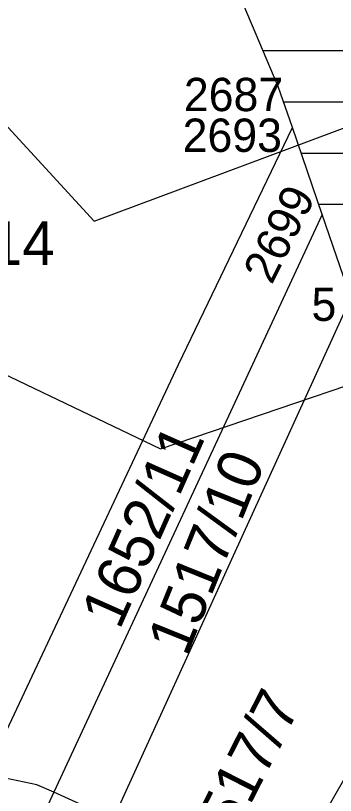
# Model space of a CAD drawing. Extents: x -553916 to -552953, y -1067469 to -1066637.
# Drawn here: x -553532.46 to -553520.01, y -1066999.11 to -1066968.69 of the extents above; entities that cross this region are included whole.
import ezdxf

# ---------------------------------------------------------------- set-up
doc = ezdxf.new("R2010")
doc.units = 0
for name, color, linetype in [('Hranice parcel', 7, 'Continuous'), ('Parcelní čísla', 7, 'Continuous'), ('Propustek', 7, 'Continuous'), ('Přejezd - štěrkové lože', 7, 'Continuous'), ('Vrstva 1', 7, 'Continuous'), ('Vrstva 60', 7, 'Continuous')]:
    doc.layers.add(name, color=color, linetype=linetype)

msp = doc.modelspace()

# ---------------------------------------------------------------- linework, layer by layer
at = {"layer": 'Hranice parcel'}
for p, q in [((-553520.52, -1066976.45), (-553530.98, -1066998.99)), ((-553519.4, -1066979.7), (-553528.66, -1067000.03)), ((-553530.98, -1066998.99), (-553538.9, -1067016.05)), ((-553528.66, -1067000.03), (-553530.98, -1066998.99))]:
    msp.add_line(p, q, dxfattribs=at)
for points in [[(-553533.63, -1066998.28), (-553526.12, -1066982.3), (-553521.68, -1066973.05)], [(-553515.43, -1066991.08), (-553526.38, -1067010.19), (-553539.65, -1067043.59), (-553548.33, -1067069.03)], [(-553530.98, -1066998.99), (-553531.64, -1066998.7), (-553533.63, -1066998.28)]]:
    msp.add_lwpolyline(points, dxfattribs=at)
at = {"layer": 'Propustek'}
msp.add_lwpolyline([(-553576.56, -1066984.514), (-553536.119, -1066969.402), (-553529.408, -1066976.709), (-553517.537, -1066972.276)], dxfattribs=at)
at = {"layer": 'Přejezd - štěrkové lože'}
msp.add_lwpolyline([(-553573.367, -1066993.961), (-553535.151, -1066981.6), (-553526.82, -1066985.587), (-553514.291, -1066981.32)], dxfattribs=at)
at = {"layer": 'Vrstva 1'}
for p, q in [((-553522.825, -1066970.052), (-553518.361, -1066970.052)), ((-553522.025, -1066972.052), (-553517.603, -1066972.052)), ((-553520.52, -1066976.45), (-553521.68, -1066973.05)), ((-553521.338, -1066974.052), (-553516.861, -1066974.052)), ((-553520.656, -1066976.052), (-553516.875, -1066976.052)), ((-553519.4, -1066979.7), (-553520.52, -1066976.45))]:
    msp.add_line(p, q, dxfattribs=at)
msp.add_lwpolyline([(-553521.68, -1066973.05), (-553522.23, -1066971.46), (-553527.43, -1066959.15)], dxfattribs=at)
at = {"layer": 'Vrstva 60'}
for p, q in [((-553522.23, -1066971.46), (-553522.23, -1066971.46)), ((-553521.68, -1066973.05), (-553521.68, -1066973.05)), ((-553520.52, -1066976.45), (-553520.52, -1066976.45))]:
    msp.add_line(p, q, dxfattribs=at)

# ---------------------------------------------------------------- texts
at = {"layer": 'Parcelní čísla'}
msp.add_text('51/14', height=1.7, dxfattribs=at).set_placement((-553536.628, -1066978.42))
for s, rotation, p in [('1652/11', 66, (-553528.413, -1066992.687)), ('1517/10', 68, (-553525.803, -1066993.733)), ('1517/7', 63, (-553524.481, -1067001.782))]:
    msp.add_text(s, height=1.7, rotation=rotation, dxfattribs=at).set_placement(p)
at = {"layer": 'Vrstva 60'}
for s, p in [('2687', (-553525.907, -1066972.418)), ('2693', (-553525.955, -1066974.008)), ('5', (-553520.936, -1066980.601))]:
    msp.add_text(s, height=1.3, dxfattribs=at).set_placement(p)
msp.add_text('2699', height=1.3, rotation=63.4431, dxfattribs=at).set_placement((-553522.484, -1066979.219))

doc.saveas('drawing.dxf')
